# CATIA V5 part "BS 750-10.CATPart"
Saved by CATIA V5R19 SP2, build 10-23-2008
Part number: BS 750-10
Bounding box of the stored display mesh (mm): x -22.494 to 22.494, y -22.494 to 22.494, z 0 to 52
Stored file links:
  C:\Users\Bora\Desktop\3D Katı model\BS serisi\BS 750\BS 750-10.CATPart
  C:\Program Files\Dassault Systemes\B19\intel_a\reffiles\standard\MetricThickPitch.txt
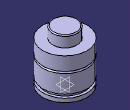
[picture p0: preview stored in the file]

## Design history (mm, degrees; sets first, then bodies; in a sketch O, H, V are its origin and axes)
Body1 (main body)
  Sketch1 on yz-plane, origin (0, 0, 0), H (0, 1, 0), V (0, 0, 1)
    point P3 (12.5, 51)
    point P5 (12.5, 51)
    point P7 (22.5, 27.5)
    point P8 (22.5, 25.5)
    point P12 (22.5, 25.5)
    point P13 (22.5, 27.5)
    line L1 (22.5, 0) -> (22.5, 4)
    line L2 (12.5, 51) -> (12.5, 41)
    arc A1 centre (11.5, 51) radius 1 from (12.5, 51) to (11.5, 52) ccw
    arc A2 centre (22.5, 26.5) radius 1 from (22.5, 27.5) to (22.5, 25.5) ccw
    line L3 (20, 7.5) -> (20, 4)
    line L4 (22.5, 7.5) -> (22.5, 25.5)
    line L5 (22.5, 27.5) -> (22.5, 41)
    line L6 (11.5, 52) -> (0, 52)
    point P15 (0, 52)
    line L7 (12.5, 41) -> (22.5, 41)
    line L8 (20, 7.5) -> (22.5, 7.5)
    line L9 (20, 4) -> (22.5, 4)
    line L10 (22.5, 0) -> (0, 0)
    coincidence: P15 V, P3 P5, P7 P13, P8 P12
    tangency: L6 A1
    horizontal: L7 H, L8 H, L9 H, L10 H
  Shaft1: profile Sketch1, axis Sketch1.V, angle 360
  Sketch2 on face of Shaft1 from Sketch1.L10, origin (0, 0, 0), H (1, 0, 0), V (0, -1, 0)
    point P1 (10, 0)
    distance P1 V = 10
  Hole1: placed by Sketch2, at (10, 0, 0) direction (0, 0, 1), diameter 6.647, depth 4, threaded "M8", thread diameter 8, thread depth 4, pitch 1.25
  CircPattern1: of Hole1, instances 2, angular step 180, axis from xy-plane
